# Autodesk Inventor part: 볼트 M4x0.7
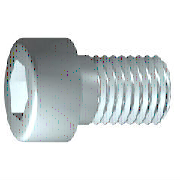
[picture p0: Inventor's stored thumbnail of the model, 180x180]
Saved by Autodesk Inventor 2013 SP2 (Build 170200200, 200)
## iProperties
IsCustomPart: 0
Created: 2015-12
Part Number: 볼트 M4x0.7
Material: 강철, 연강
Description: 6각머리 태핑 나사
Document SubType Name: Modeling
Standard: KS B 1003
Designer: mdu
Standards Organization: KS
Language: ko-KR
Size Designation: M 4 x 12
Categories: <MemberInstance><Categories><Category DisplayName="조임쇠" InternalName="e4da775c-781d-43d5-af7c-5136215cf5a6" Mnemonic="FSTN"><Category DisplayName="볼트" InternalN
Density: 7.86 g/cm^3
Mass: 2.23465 g
Surface Area: 3.30853 cm^2
Volume: 0.284306 cm^3
Author: mdu
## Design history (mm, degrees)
sketch "스케치1"
  geometry: L1 (-1, 0)-(12, 0); L2 (12, 0)-(12, 2); L3 (12, 2)-(1.75, 2); L4 (1.75, 2)-(1.32, 2); L5 (1.32, 2)-(0, 2); L6 (0, 2)-(0, 3.5); L7 (0, 3.5)-(-4, 3.5); L8 (-4, 3.5)-(-4, 1.732); L9 (-4, 1.732)-(-2, 1.732); L10 (-2, 1.732)-(-1, 0); L11 (-7.2, 0)-(15.2, 0) reference; L12 (0, -0.7)-(0, 4.2) reference; L13 (1.75, 2)-(0, 2)
  constraints: 22 end point, 6 parallel, 2 collinear, 2 perpendicular, 1 horizontal, 1 point on line
  dimensions: "d1" = 10.25 distance from line of L3.end L2 (= GEL); "d2" = 0.42952 distance of L4.end L3.end (computed from GAL); "d3" = 4 distance between parallel lines of L8 L6 (= KOH); "d4" = 2 distance of L8.end L9.end (= INTI); "d5" = 60 deg angle of L10 L1; "d6" = 4 diameter of L3 L1 (= GD); "d7" = 4 diameter of L5 L1 (= BDM); "d8" = 3.4641 diameter of L9 L1 (= 1.1547 x SW); "d9" = 7 diameter of L7 L1 (= KOD); "d26" = 12 distance between parallel lines of L12 L2 (= NLG)
revolve "본체" sketch "스케치1" stored, may be unused: angle "d10" = 90 deg
sketch "스케치2"
  geometry: L1 (0, -4.9)-(0, 4.9) reference; L2 (-4.9, 0)-(4.9, 0) reference; L3 (1.732, 0)-(0.866, -1.5); L4 (0.866, -1.5)-(-0.866, -1.5); L5 (-0.866, -1.5)-(-1.732, 0); L6 (-1.732, 0)-(-0.866, 1.5); L7 (-0.866, 1.5)-(0.866, 1.5); L8 (0.866, 1.5)-(1.732, 0); 2 further points
  constraints: 12 end point, 1 coincident, 1 horizontal alignment, 1 point on line, 12 other
extrude "슬롯" join sketch "스케치2" stored distance "d11" = 10; taper "d12" = 0 deg
workplane "Work Plane1"
fillet "Fillet2" dims "d30" = 0.1 (= R)
body "Solid1"
fillet "모깎기1" dims "d17" = 0.4 (= RR)
feature "스레드" dims "d13" = 10.25 (= GEL), "d14" = 0
chamfer "모따기1" distance "d15" = 0.42941 (= -0.5 x SPD + 0.5 x GD); stored, may be unused: second distance "d16" = 0.42941 (= GUL), angle "d27" = 45 deg
other parameters: "GD" = 4 (= NND) [user parameter; used in 2 equation terms], "NLG" = 12 [user parameter; used in 1 equation term], "GEL" = 10.25 [user parameter; used in 2 equation terms], "KOD" = 7 [user parameter; used in 1 equation term], "KOH" = 4 [user parameter; used in 1 equation term], "INTI" = 2 [user parameter; used in 1 equation term], "GAL" = 0.42941 (= 0.61345 x PTC) [user parameter; used in 1 equation term], "GUL" = 0.42941 (= 0.61345 x PTC) [user parameter; used in 1 equation term], "BDM" = 4 (= NND) [user parameter; used in 1 equation term], "SW" = 3 [user parameter; used in 2 equation terms], "RR" = 0.4 [user parameter; used in 1 equation term], "SPD" = 3.14117 (= NND - 1.2269 x PTC) [user parameter; used in 1 equation term], "d19" = 0, "d28" = 0, "d29" = 0, "R" = 0.1 [user parameter; used in 1 equation term], "PHH" = 0.2 [user parameter], "GD1" = 3.14117 (= THREADDIA - 1.2269 x PTC) [user parameter], "THREADDIA" = 4 [user parameter; used in 1 equation term], "FAWI" = 45 deg [user parameter], "TPU" = 14.28571 (computed from PTC) [user parameter], "PTC" = 0.7 [user parameter; used in 5 equation terms], "NND" = 4 [user parameter; used in 3 equation terms], "TOA" = 30 deg [user parameter], "E0" = 3.465 (= 1.155 x SW) [user parameter]
